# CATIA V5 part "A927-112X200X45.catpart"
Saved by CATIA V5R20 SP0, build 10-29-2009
Part number: A927-112X200X45
Source: Unknown
Property "A": "50.000"
Property "ARTICLENO": "A927-112X200X45"
Property "BOMINFO": "A927-112X200X45"
Property "CODE": "A927-112X200X45"
Property "CREATOR": "CADENAS GmbH"
Property "D": "18.000"
Property "D1": "26.000"
Property "F": "28.000"
Property "FORM": "A"
Property "L": "200.000"
Property "L1": "100.000"
Property "L2": "20.000"
Property "L3": "50.000"
Property "LINA": "A927-112X200X45"
Property "NB": "A927-112X200X45"
Property "NBSYN": "$CODE."
Property "NN": "A927"
Property "NT": "VDI 3387 Removable Die Heels, steel and self-lubricating"
Property "R": "25.000"
Property "S": "45.000"
Property "SUPPLIER": "CF"
Property "T": "21.000"
Property "W": "112.000"
Bounding box of the stored display mesh (mm): x -56 to 56, y 0 to 200, z -45 to 0
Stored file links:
  C:\Users\borellobunino\Desktop\3D X SITO CF\A927\GSB_OILLESS_G2290511220045\CATIAV5\A927-112X200X45.catpart
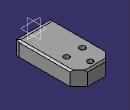
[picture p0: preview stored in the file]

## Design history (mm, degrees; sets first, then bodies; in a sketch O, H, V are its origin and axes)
Body1 "Geometry.1" (main body)
  Solid1 "A927-112X200X45.catpart": solid without history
